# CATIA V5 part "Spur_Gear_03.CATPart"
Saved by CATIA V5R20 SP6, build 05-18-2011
Part number: Spur_Gear_03
Bounding box of the stored display mesh (mm): x 21 to 25, y -18.961 to -3.823, z -14.09 to 1.08
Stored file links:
  E:\#01 CATIA Lecture Materials\#06 DMU\#16 DMU Page01 KIN EX16\Spur_Gear_03.CATPart
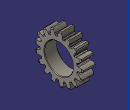
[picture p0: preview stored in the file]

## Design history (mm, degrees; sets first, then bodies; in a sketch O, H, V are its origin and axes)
Set1
  Sketch1, origin (0, 0, 0), H (0, 1, 0), V (0, 0, 1), geometry linked from another document
Body1 (main body)
Body2
  Solid1: solid without history
  Translate1: Direction Sketch1, Length 3.15, ToTransfor Solid1
  Sketch2 on face of Solid1, origin (25.5, -13.8053, -3.5717), H (0, 1, 0), V (0, 0, 1)
    point P1 (2.3827, -2.9435)
    reference projected circle E1 centre (2.3827, -2.9435) radius 4.5 from edge [face of Solid1 | face of Solid1]
    concentricity: E1 P1
  Hole1: placed by Sketch2, at (25.5, -11.4226, -6.5152) direction (-1, 0, 0), diameter 9, through (limit type 6)
  Chamfer1: length 0.15, angle 45, on face of Hole1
